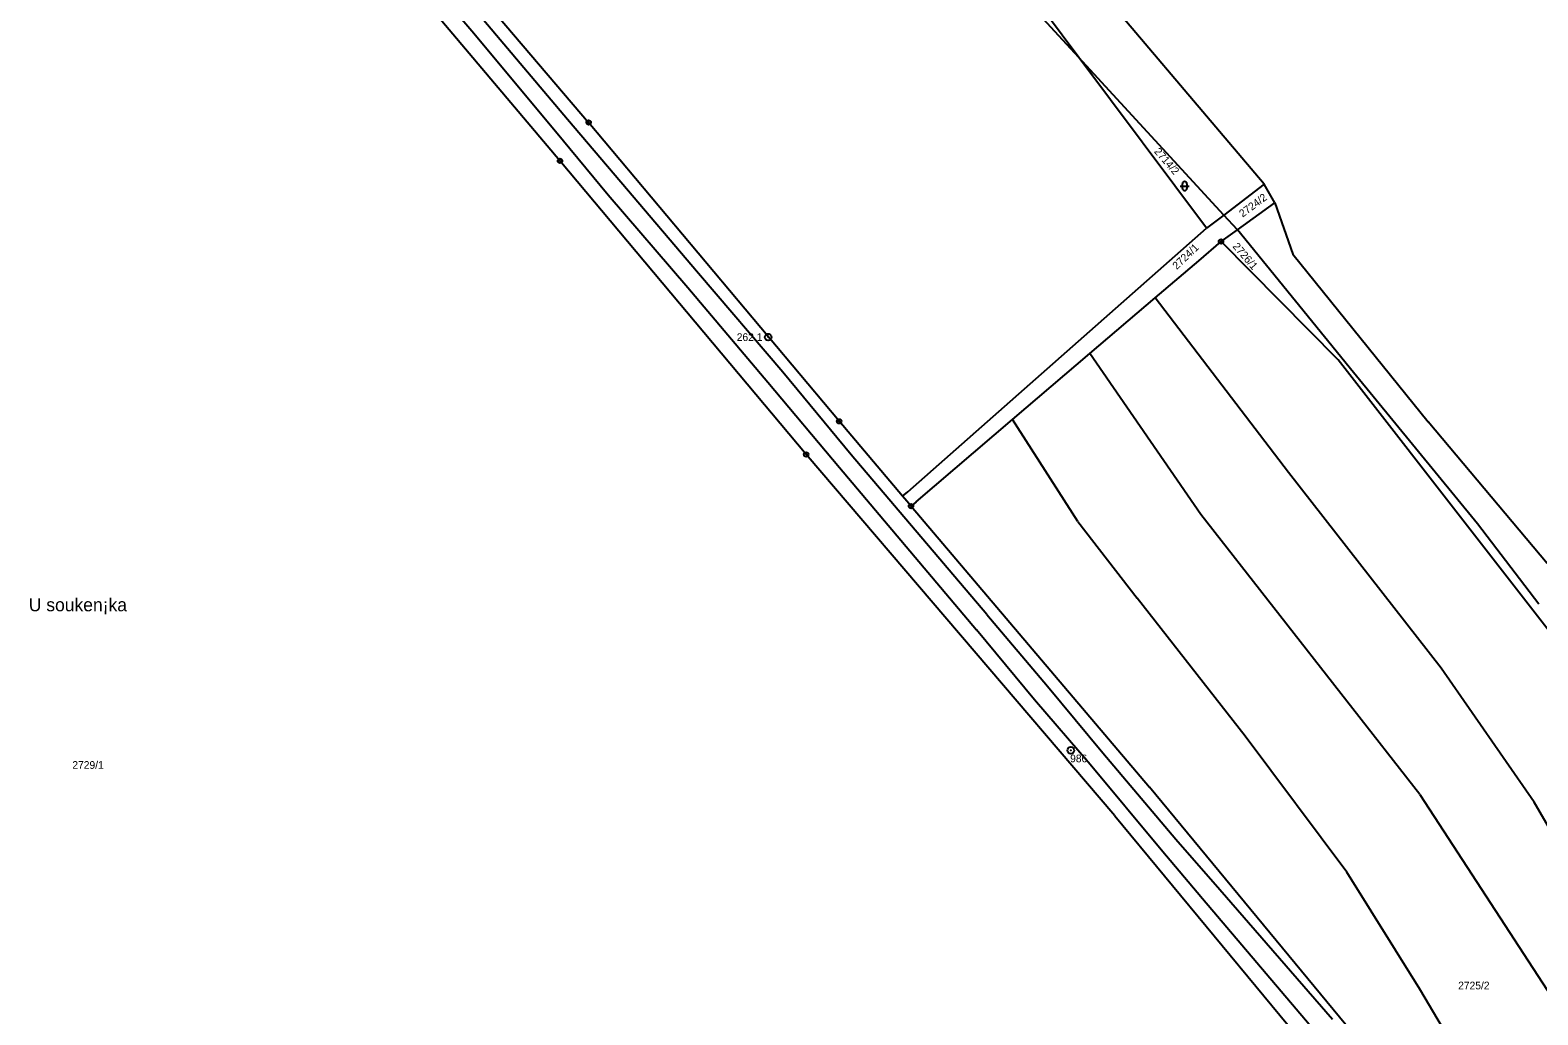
# Model space of a CAD drawing. Extents: x -736345 to -729997, y -1130177 to -1122501.
# Drawn here: x -734571.9 to -734237.6, y -1125006.7 to -1124788.5 of the extents above; entities that cross this region are included whole.
import ezdxf

# ---------------------------------------------------------------- set-up
doc = ezdxf.new("R2010")
doc.units = 0
for name, color, linetype in [('Vrstva 1', 7, 'Continuous'), ('Vrstva 15', 7, 'Continuous'), ('Vrstva 17', 7, 'Continuous'), ('Vrstva 18', 7, 'Continuous'), ('Vrstva 25', 7, 'Continuous'), ('Vrstva 4', 7, 'Continuous')]:
    doc.layers.add(name, color=color, linetype=linetype)

msp = doc.modelspace()

# ---------------------------------------------------------------- linework, layer by layer
at = {"layer": 'Vrstva 1'}
for points in [[(-734512.45, -1124733.39), (-734448.03, -1124808.93)], [(-734454.39, -1124817.45), (-734519.99, -1124739.83)], [(-734298.26, -1124822.62), (-734342.38, -1124770.54)], [(-734339.3, -1124794.55), (-734351.7, -1124781.07)], [(-734339.3, -1124794.55), (-734350.44, -1124779.64)], [(-734311.03, -1124832.38), (-734339.3, -1124794.55)], [(-734307.19, -1124829.44), (-734339.3, -1124794.55)], [(-734392.49, -1124875.16), (-734448.03, -1124808.93)], [(-734399.79, -1124882.5), (-734454.39, -1124817.45)], [(-734298.26, -1124822.62), (-734307.19, -1124829.44)], [(-734295.9, -1124826.73), (-734298.26, -1124822.62)], [(-734307.19, -1124829.44), (-734311.03, -1124832.38)], [(-734304.18, -1124832.71), (-734307.19, -1124829.44)], [(-734304.18, -1124832.71), (-734295.9, -1124826.73)], [(-734295.9, -1124826.73), (-734291.86, -1124838.12)], [(-734377.27, -1124890.76), (-734311.03, -1124832.38)], [(-734307.81, -1124835.32), (-734304.18, -1124832.71)], [(-734278.41, -1124864.37), (-734304.18, -1124832.71)], [(-734312.72, -1124839.56), (-734307.81, -1124835.32)], [(-734281.85, -1124861.53), (-734307.81, -1124835.32)], [(-734322.42, -1124847.83), (-734312.72, -1124839.56)], [(-734291.86, -1124838.12), (-734261.84, -1124875.31)], [(-734336.86, -1124860.14), (-734322.42, -1124847.83)], [(-734292.84, -1124886.52), (-734322.42, -1124847.83)], [(-734354.03, -1124874.77), (-734336.86, -1124860.14)], [(-734312.31, -1124895.84), (-734336.86, -1124860.14)], [(-734217.72, -1124943.88), (-734281.85, -1124861.53)], [(-734250.96, -1124897.89), (-734278.41, -1124864.37)], [(-734378.4, -1124891.75), (-734392.49, -1124875.16)], [(-734375.42, -1124893), (-734354.03, -1124874.77)], [(-734339.59, -1124897.36), (-734354.03, -1124874.77)], [(-734235.52, -1124906.7), (-734261.84, -1124875.31)], [(-734331.36, -1124962.57), (-734399.79, -1124882.5)], [(-734258.96, -1124929.88), (-734292.84, -1124886.52)], [(-734378.4, -1124891.75), (-734377.27, -1124890.76)], [(-734376.54, -1124893.95), (-734378.4, -1124891.75)], [(-734375.42, -1124893), (-734376.54, -1124893.95)], [(-734376.54, -1124893.95), (-734323.7, -1124956.2)], [(-734263.69, -1124957.87), (-734312.31, -1124895.84)], [(-734339.59, -1124897.36), (-734326.39, -1124914.35)], [(-734237.3, -1124915.69), (-734250.96, -1124897.89)], [(-734302.48, -1124944.94), (-734326.39, -1124914.35)], [(-734238.37, -1124959.53), (-734258.96, -1124929.88)], [(-734279.92, -1124975.07), (-734302.48, -1124944.94)], [(-734261.91, -1125030.98), (-734323.7, -1124956.2)], [(-734263.69, -1124957.87), (-734229.2, -1125010.84)], [(-734214.62, -1125000.39), (-734238.37, -1124959.53)], [(-734331.36, -1124962.57), (-734265.26, -1125042.37)], [(-734263.75, -1125001.03), (-734279.92, -1124975.07)], [(-734248.4, -1125026.83), (-734263.75, -1125001.03)]]:
    msp.add_lwpolyline(points, dxfattribs=at)
at = {"layer": 'Vrstva 25'}
for points in [[(-734316.37, -1124823.54), (-734316.37, -1124822.54)], [(-734315.37, -1124822.54), (-734315.37, -1124823.54)], [(-734316.87, -1124823.04), (-734314.87, -1124823.04)]]:
    msp.add_lwpolyline(points, dxfattribs=at)
for centre, radius in [((-734448.03, -1124808.93), 0.5), ((-734448.03, -1124808.93), 0.032), ((-734454.39, -1124817.45), 0.5), ((-734454.39, -1124817.45), 0.032), ((-734307.81, -1124835.32), 0.5), ((-734307.81, -1124835.32), 0.032), ((-734408.21, -1124856.5), 0.75), ((-734408.21, -1124856.5), 0.032), ((-734392.49, -1124875.16), 0.5), ((-734392.49, -1124875.16), 0.032), ((-734399.79, -1124882.5), 0.5), ((-734399.79, -1124882.5), 0.032), ((-734376.54, -1124893.95), 0.5), ((-734376.54, -1124893.95), 0.032), ((-734341.11, -1124948.08), 0.75), ((-734341.11, -1124948.08), 0.032)]:
    msp.add_circle(centre, radius, dxfattribs=at)
for centre, start, end in [((-734315.87, -1124822.54), 0.10099, 180.00143), ((-734315.87, -1124823.54), 180.10243, 0.00286)]:
    msp.add_arc(centre, 0.5, start, end, dxfattribs=at)
at = {"layer": 'Vrstva 4'}
for points in [[(-734495.28, -1124763.6), (-734473.91, -1124788.65)], [(-734473.91, -1124788.65), (-734455.39, -1124810.83)], [(-734452.71, -1124808.25), (-734471.23, -1124786.33)], [(-734440.91, -1124822.16), (-734452.71, -1124808.25)], [(-734455.39, -1124810.83), (-734443.69, -1124824.95)], [(-734423.66, -1124842.4), (-734440.91, -1124822.16)], [(-734443.69, -1124824.95), (-734426, -1124845.48)], [(-734404.97, -1124864.26), (-734423.66, -1124842.4)], [(-734426, -1124845.48), (-734408.28, -1124866.46)], [(-734389.84, -1124882.58), (-734404.97, -1124864.26)], [(-734408.28, -1124866.46), (-734392.38, -1124885.4)], [(-734359.72, -1124917.97), (-734389.84, -1124882.58)], [(-734392.38, -1124885.4), (-734362, -1124921.38)], [(-734359.72, -1124917.97), (-734346.28, -1124933.89)], [(-734349.15, -1124936.86), (-734362, -1124921.38)], [(-734346.28, -1124933.89), (-734334.04, -1124948.6)], [(-734336.83, -1124951.2), (-734349.15, -1124936.86)], [(-734334.04, -1124948.6), (-734317.8, -1124967.74)], [(-734321.05, -1124970.11), (-734336.83, -1124951.2)], [(-734317.8, -1124967.74), (-734308.08, -1124978.93)], [(-734311.9, -1124980.98), (-734321.05, -1124970.11)], [(-734308.08, -1124978.93), (-734283.09, -1125007.68)], [(-734285.77, -1125011.79), (-734311.9, -1124980.98)]]:
    msp.add_lwpolyline(points, dxfattribs=at)

# ---------------------------------------------------------------- texts
at = {"layer": 'Vrstva 15'}
msp.add_text('U souken¡ka', height=2.89999, dxfattribs=at).set_placement((-734572.16, -1124917.26))
at = {"layer": 'Vrstva 17'}
for s, p in [('262.1', (-734415.181, -1124857.35)), ('986', (-734341.26, -1124950.72))]:
    msp.add_text(s, height=1.7, dxfattribs=at).set_placement(p)
at = {"layer": 'Vrstva 18'}
for s, rotation, p in [('2714/2', 311.00247, (-734322.748, -1124815.439)), ('2724/2', 36.60029, (-734303.019, -1124830.041)), ('2724/1', 43.60035, (-734317.614, -1124841.638)), ('2726/1', 310.70247, (-734305.338, -1124836.461))]:
    msp.add_text(s, height=1.7, rotation=rotation, dxfattribs=at).set_placement(p)
for s, p in [('2729/1', (-734562.5, -1124952.17)), ('2725/2', (-734255.22, -1125001.04))]:
    msp.add_text(s, height=1.7, dxfattribs=at).set_placement(p)

doc.saveas('drawing.dxf')
